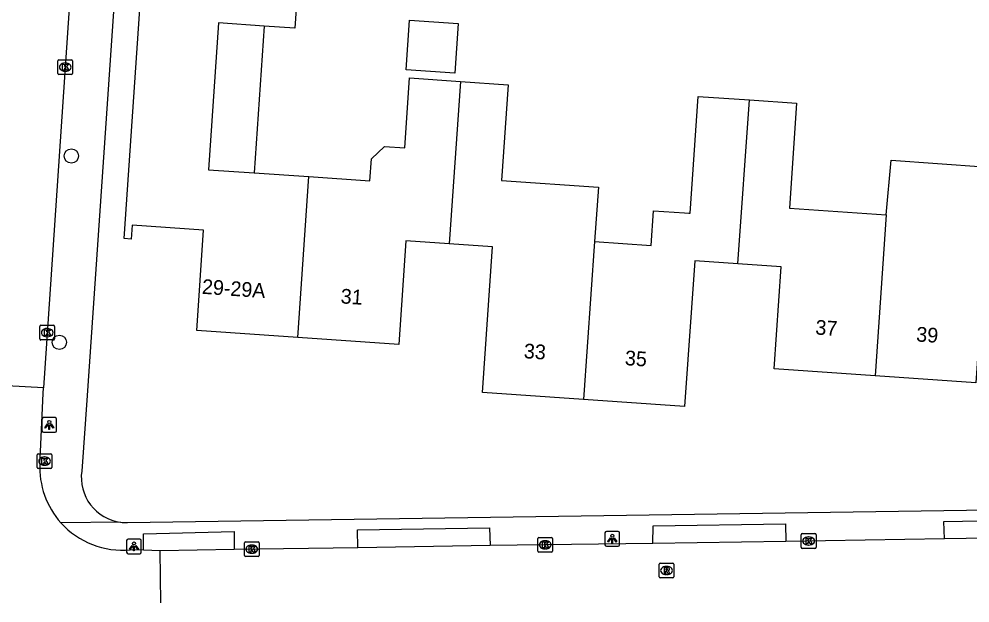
# Model space of a CAD drawing. Extents: x 161848 to 162726, y 385382 to 386521.
# Drawn here: x 162274 to 162338.6, y 385386.6 to 385426.3 of the extents above; entities that cross this region are included whole.
import ezdxf

# ---------------------------------------------------------------- set-up
doc = ezdxf.new("R2010")
doc.units = 0
for name, color, linetype in [('IMGEO_Boom', 7, 'Continuous'), ('IMGEO_Kolk', 7, 'Continuous'), ('IMGEO_Lichtpunt', 7, 'Continuous'), ('IMGEO_Pand', 7, 'Continuous'), ('IMGEO_Pand_nummerreeks', 7, 'Continuous'), ('IMGEO_Rijbaan_lokaal_open', 7, 'Continuous'), ('IMGEO_Rioolput', 7, 'Continuous'), ('IMGEO_Voetpad_open', 7, 'Continuous')]:
    doc.layers.add(name, color=color, linetype=linetype)

msp = doc.modelspace()

# ---------------------------------------------------------------- linework, layer by layer
at = {"layer": 'IMGEO_Boom'}
for centre in [(162277.545, 385416.99), (162276.731, 385404.331)]:
    msp.add_circle(centre, 0.489, dxfattribs=at)
at = {"layer": 'IMGEO_Kolk'}
for p, q in [((162276.631, 385422.602), (162276.631, 385423.454)), ((162276.706, 385423.528), (162277.558, 385423.528)), ((162277.632, 385423.454), (162277.632, 385422.602)), ((162277.119, 385423.308), (162277.144, 385423.308)), ((162277.558, 385422.528), (162276.706, 385422.528)), ((162277.142, 385422.748), (162277.117, 385422.748)), ((162275.409, 385404.563), (162275.409, 385405.415)), ((162275.484, 385405.489), (162276.336, 385405.489)), ((162276.41, 385405.415), (162276.41, 385404.563)), ((162275.92, 385404.709), (162275.895, 385404.709)), ((162275.897, 385405.269), (162275.922, 385405.269)), ((162276.336, 385404.489), (162275.484, 385404.489)), ((162275.228, 385395.837), (162275.228, 385396.689)), ((162275.303, 385396.763), (162276.155, 385396.763)), ((162275.716, 385396.543), (162275.741, 385396.543)), ((162276.229, 385396.689), (162276.229, 385395.837)), ((162276.155, 385395.763), (162275.303, 385395.763)), ((162275.739, 385395.983), (162275.714, 385395.983)), ((162327.121, 385390.409), (162327.121, 385391.261)), ((162327.196, 385391.335), (162328.048, 385391.335)), ((162328.122, 385391.261), (162328.122, 385390.409)), ((162289.299, 385389.853), (162289.299, 385390.705)), ((162289.374, 385390.779), (162290.226, 385390.779)), ((162289.787, 385390.559), (162289.812, 385390.559)), ((162290.3, 385390.705), (162290.3, 385389.853)), ((162309.227, 385390.15), (162309.227, 385391.002)), ((162309.302, 385391.076), (162310.154, 385391.076)), ((162309.715, 385390.856), (162309.74, 385390.856)), ((162310.228, 385391.002), (162310.228, 385390.15)), ((162327.632, 385390.555), (162327.607, 385390.555)), ((162327.609, 385391.115), (162327.634, 385391.115)), ((162289.81, 385389.999), (162289.785, 385389.999)), ((162310.154, 385390.076), (162309.302, 385390.076)), ((162309.738, 385390.296), (162309.713, 385390.296)), ((162328.048, 385390.335), (162327.196, 385390.335)), ((162290.226, 385389.779), (162289.374, 385389.779))]:
    msp.add_line(p, q, dxfattribs=at)
for points in [[(162276.631, 385422.602), (162276.631, 385423.454)], [(162276.706, 385423.528), (162277.558, 385423.528)], [(162277.632, 385423.454), (162277.632, 385422.602)], [(162276.952, 385423.228), (162277.075, 385423.228), (162277.075, 385423.077), (162277.205, 385423.228), (162277.369, 385423.228), (162277.223, 385423.077), (162277.376, 385422.828), (162277.224, 385422.828), (162277.139, 385422.992), (162277.075, 385422.925), (162277.075, 385422.828), (162276.952, 385422.828), (162276.952, 385423.228)], [(162277.558, 385422.528), (162276.706, 385422.528)], [(162275.409, 385404.563), (162275.409, 385405.415)], [(162275.484, 385405.489), (162276.336, 385405.489)], [(162276.41, 385405.415), (162276.41, 385404.563)], [(162275.73, 385405.189), (162275.853, 385405.189), (162275.853, 385405.038), (162275.983, 385405.189), (162276.147, 385405.189), (162276.001, 385405.038), (162276.154, 385404.789), (162276.002, 385404.789), (162275.917, 385404.953), (162275.853, 385404.886), (162275.853, 385404.789), (162275.73, 385404.789), (162275.73, 385405.189)], [(162276.336, 385404.489), (162275.484, 385404.489)], [(162275.228, 385395.837), (162275.228, 385396.689)], [(162275.303, 385396.763), (162276.155, 385396.763)], [(162275.549, 385396.463), (162275.672, 385396.463), (162275.672, 385396.312), (162275.802, 385396.463), (162275.966, 385396.463), (162275.82, 385396.312), (162275.973, 385396.063), (162275.821, 385396.063), (162275.736, 385396.227), (162275.672, 385396.16), (162275.672, 385396.063), (162275.549, 385396.063), (162275.549, 385396.463)], [(162276.229, 385396.689), (162276.229, 385395.837)], [(162276.155, 385395.763), (162275.303, 385395.763)], [(162327.121, 385390.409), (162327.121, 385391.261)], [(162327.196, 385391.335), (162328.048, 385391.335)], [(162328.122, 385391.261), (162328.122, 385390.409)], [(162289.299, 385389.853), (162289.299, 385390.705)], [(162289.374, 385390.779), (162290.226, 385390.779)], [(162290.3, 385390.705), (162290.3, 385389.853)], [(162309.227, 385390.15), (162309.227, 385391.002)], [(162309.302, 385391.076), (162310.154, 385391.076)], [(162309.548, 385390.776), (162309.671, 385390.776), (162309.671, 385390.625), (162309.801, 385390.776), (162309.965, 385390.776), (162309.819, 385390.625), (162309.972, 385390.376), (162309.82, 385390.376), (162309.735, 385390.54), (162309.671, 385390.473), (162309.671, 385390.376), (162309.548, 385390.376), (162309.548, 385390.776)], [(162310.228, 385391.002), (162310.228, 385390.15)], [(162327.442, 385391.035), (162327.565, 385391.035), (162327.565, 385390.884), (162327.695, 385391.035), (162327.859, 385391.035), (162327.713, 385390.884), (162327.866, 385390.635), (162327.714, 385390.635), (162327.629, 385390.799), (162327.565, 385390.732), (162327.565, 385390.635), (162327.442, 385390.635), (162327.442, 385391.035)], [(162289.62, 385390.479), (162289.743, 385390.479), (162289.743, 385390.328), (162289.873, 385390.479), (162290.037, 385390.479), (162289.891, 385390.328), (162290.044, 385390.079), (162289.892, 385390.079), (162289.807, 385390.243), (162289.743, 385390.176), (162289.743, 385390.079), (162289.62, 385390.079), (162289.62, 385390.479)], [(162310.154, 385390.076), (162309.302, 385390.076)], [(162328.048, 385390.335), (162327.196, 385390.335)], [(162290.226, 385389.779), (162289.374, 385389.779)]]:
    msp.add_lwpolyline(points, dxfattribs=at)
for centre, start, end in [((162276.708, 385423.452), 91.55205, 178.44795), ((162276.708, 385423.452), 91.55205, 178.44795), ((162277.556, 385423.452), 1.55205, 88.44795), ((162277.556, 385423.452), 1.55205, 88.44795), ((162276.708, 385422.604), 181.55205, 268.44795), ((162276.708, 385422.604), 181.55205, 268.44795), ((162277.556, 385422.604), 271.55205, 358.44795), ((162277.556, 385422.604), 271.55205, 358.44795), ((162275.486, 385405.413), 91.55205, 178.44795), ((162275.486, 385405.413), 91.55205, 178.44795), ((162276.334, 385405.413), 1.55205, 88.44795), ((162276.334, 385405.413), 1.55205, 88.44795), ((162275.486, 385404.565), 181.55205, 268.44795), ((162275.486, 385404.565), 181.55205, 268.44795), ((162276.334, 385404.565), 271.55205, 358.44795), ((162276.334, 385404.565), 271.55205, 358.44795), ((162275.305, 385396.687), 91.55205, 178.44795), ((162275.305, 385396.687), 91.55205, 178.44795), ((162276.153, 385396.687), 1.55205, 88.44795), ((162276.153, 385396.687), 1.55205, 88.44795), ((162275.305, 385395.839), 181.55205, 268.44795), ((162275.305, 385395.839), 181.55205, 268.44795), ((162276.153, 385395.839), 271.55205, 358.44795), ((162276.153, 385395.839), 271.55205, 358.44795), ((162327.198, 385391.259), 91.55205, 178.44795), ((162327.198, 385391.259), 91.55205, 178.44795), ((162328.046, 385391.259), 1.55205, 88.44795), ((162328.046, 385391.259), 1.55205, 88.44795), ((162289.376, 385390.703), 91.55205, 178.44795), ((162289.376, 385390.703), 91.55205, 178.44795), ((162290.224, 385390.703), 1.55205, 88.44795), ((162290.224, 385390.703), 1.55205, 88.44795), ((162309.304, 385391), 91.55205, 178.44795), ((162309.304, 385391), 91.55205, 178.44795), ((162310.152, 385391), 1.55205, 88.44795), ((162310.152, 385391), 1.55205, 88.44795), ((162289.376, 385389.855), 181.55205, 268.44795), ((162289.376, 385389.855), 181.55205, 268.44795), ((162290.224, 385389.855), 271.55205, 358.44795), ((162290.224, 385389.855), 271.55205, 358.44795), ((162309.304, 385390.152), 181.55205, 268.44795), ((162309.304, 385390.152), 181.55205, 268.44795), ((162310.152, 385390.152), 271.55205, 358.44795), ((162310.152, 385390.152), 271.55205, 358.44795), ((162327.198, 385390.411), 181.55205, 268.44795), ((162327.198, 385390.411), 181.55205, 268.44795), ((162328.046, 385390.411), 271.55205, 358.44795), ((162328.046, 385390.411), 271.55205, 358.44795)]:
    msp.add_arc(centre, 0.0765, start, end, dxfattribs=at)
for centre, major_axis, ratio, start_param, end_param in [((162277.118, 385423.028), (-0.387, 0.002), 0.722429, 4.712389, 7.853982), ((162277.143, 385423.028), (-0.39, 0.002), 0.717154, 1.570796, 4.712389), ((162275.896, 385404.989), (-0.387, 0.002), 0.722429, 4.712389, 7.853982), ((162275.921, 385404.989), (-0.39, 0.002), 0.717154, 1.570796, 4.712389), ((162275.715, 385396.263), (-0.387, 0.002), 0.722429, 4.712389, 7.853982), ((162275.74, 385396.263), (-0.39, 0.002), 0.717154, 1.570796, 4.712389), ((162289.786, 385390.279), (-0.387, 0.002), 0.722429, 4.712389, 7.853982), ((162289.811, 385390.279), (-0.39, 0.002), 0.717154, 1.570796, 4.712389), ((162309.714, 385390.576), (-0.387, 0.002), 0.722429, 4.712389, 7.853982), ((162309.739, 385390.576), (-0.39, 0.002), 0.717154, 1.570796, 4.712389), ((162327.608, 385390.835), (-0.387, 0.002), 0.722429, 4.712389, 7.853982), ((162327.633, 385390.835), (-0.39, 0.002), 0.717154, 1.570796, 4.712389)]:
    msp.add_ellipse(centre, major_axis=major_axis, ratio=ratio, start_param=start_param, end_param=end_param, dxfattribs=at)
at = {"layer": 'IMGEO_Lichtpunt'}
for p, q in [((162275.55, 385399.121), (162275.55, 385398.314)), ((162275.55, 385399.121), (162275.55, 385398.314)), ((162276.452, 385399.216), (162275.644, 385399.216)), ((162276.452, 385399.216), (162275.644, 385399.216)), ((162276.546, 385398.314), (162276.546, 385399.121)), ((162276.546, 385398.314), (162276.546, 385399.121)), ((162275.644, 385398.22), (162276.452, 385398.22)), ((162275.644, 385398.22), (162276.452, 385398.22)), ((162313.787, 385391.39), (162313.787, 385390.583)), ((162313.787, 385391.39), (162313.787, 385390.583)), ((162314.689, 385391.485), (162313.881, 385391.485)), ((162314.689, 385391.485), (162313.881, 385391.485)), ((162314.783, 385390.583), (162314.783, 385391.39)), ((162314.783, 385390.583), (162314.783, 385391.39)), ((162281.3, 385390.874), (162281.3, 385390.067)), ((162281.3, 385390.874), (162281.3, 385390.067)), ((162282.202, 385390.969), (162281.394, 385390.969)), ((162282.202, 385390.969), (162281.394, 385390.969)), ((162282.296, 385390.067), (162282.296, 385390.874)), ((162282.296, 385390.067), (162282.296, 385390.874)), ((162313.881, 385390.489), (162314.689, 385390.489)), ((162313.881, 385390.489), (162314.689, 385390.489)), ((162281.394, 385389.973), (162282.202, 385389.973)), ((162281.394, 385389.973), (162282.202, 385389.973))]:
    msp.add_line(p, q, dxfattribs=at)
for points in [[(162275.924, 385398.785), (162275.963, 385398.757), (162275.775, 385398.495), (162275.737, 385398.522), (162275.924, 385398.785)], [(162276.026, 385398.737), (162276.073, 385398.737), (162276.073, 385398.415), (162276.026, 385398.415), (162276.026, 385398.737)], [(162276.136, 385398.757), (162276.174, 385398.784), (162276.361, 385398.522), (162276.322, 385398.494), (162276.136, 385398.757)], [(162281.674, 385390.538), (162281.713, 385390.51), (162281.525, 385390.248), (162281.487, 385390.275), (162281.674, 385390.538)], [(162281.776, 385390.49), (162281.823, 385390.49), (162281.823, 385390.168), (162281.776, 385390.168), (162281.776, 385390.49)], [(162281.886, 385390.51), (162281.924, 385390.537), (162282.111, 385390.275), (162282.072, 385390.247), (162281.886, 385390.51)], [(162314.161, 385391.054), (162314.2, 385391.026), (162314.012, 385390.764), (162313.974, 385390.791), (162314.161, 385391.054)], [(162314.263, 385391.006), (162314.31, 385391.006), (162314.31, 385390.684), (162314.263, 385390.684), (162314.263, 385391.006)], [(162314.373, 385391.026), (162314.411, 385391.053), (162314.598, 385390.791), (162314.559, 385390.763), (162314.373, 385391.026)]]:
    msp.add_lwpolyline(points, dxfattribs=at)
for centre in [(162276.049, 385398.919), (162314.286, 385391.188), (162281.799, 385390.672)]:
    msp.add_circle(centre, 0.0994, dxfattribs=at)
for centre, start, end in [((162275.644, 385399.121), 90, 180), ((162275.644, 385399.121), 90, 180), ((162276.452, 385399.121), 0, 90), ((162276.452, 385399.121), 0, 90), ((162275.644, 385398.314), 180, 270), ((162275.644, 385398.314), 180, 270), ((162276.452, 385398.314), 270, 0), ((162276.452, 385398.314), 270, 360), ((162313.881, 385391.39), 90, 180), ((162313.881, 385391.39), 90, 180), ((162314.689, 385391.39), 0, 90), ((162314.689, 385391.39), 0, 90), ((162281.394, 385390.874), 90, 180), ((162281.394, 385390.874), 90, 180), ((162282.202, 385390.874), 0, 90), ((162282.202, 385390.874), 0, 90), ((162313.881, 385390.583), 180, 270), ((162313.881, 385390.583), 180, 270), ((162314.689, 385390.583), 270, 0), ((162314.689, 385390.583), 270, 360), ((162281.394, 385390.067), 180, 270), ((162281.394, 385390.067), 180, 270), ((162282.202, 385390.067), 270, 0), ((162282.202, 385390.067), 270, 360)]:
    msp.add_arc(centre, 0.0946, start, end, dxfattribs=at)
at = {"layer": 'IMGEO_Pand'}
for points in [[(162292.921, 385404.655), (162286.06, 385405.127), (162286.529, 385411.952), (162281.684, 385412.285), (162281.619, 385411.343), (162281.132, 385411.376), (162282.593, 385432.629), (162287.974, 385432.259), (162293.149, 385431.904), (162292.721, 385425.669), (162290.635, 385425.812)], [(162290.635, 385425.812), (162287.545, 385426.024), (162286.86, 385416.057), (162289.951, 385415.844)], [(162300.29, 385422.84), (162300.521, 385426.209), (162303.814, 385425.983), (162303.582, 385422.614), (162300.29, 385422.84)], [(162290.635, 385425.812), (162289.951, 385415.844)], [(162293.68, 385415.588), (162297.818, 385415.304), (162297.921, 385416.801), (162298.813, 385417.629), (162300.187, 385417.535), (162300.513, 385422.289), (162303.976, 385422.051)], [(162332.888, 385412.984), (162333.214, 385416.701), (162339.508, 385416.248), (162339.955, 385422.748), (162343.381, 385422.512)], [(162303.976, 385422.051), (162303.21, 385411.026)], [(162303.976, 385422.051), (162307.206, 385421.829), (162306.759, 385415.326), (162313.34, 385414.873), (162313.082, 385411.171)], [(162313.082, 385411.171), (162316.933, 385410.907), (162317.095, 385413.273), (162319.181, 385413.129), (162319.49, 385413.108), (162319.567, 385413.103), (162320.112, 385421.036), (162323.593, 385420.797)], [(162322.82, 385409.668), (162323.593, 385420.797)], [(162323.593, 385420.797), (162326.805, 385420.576), (162326.314, 385413.436), (162332.888, 385412.984)], [(162289.951, 385415.844), (162293.68, 385415.588)], [(162292.921, 385404.655), (162293.68, 385415.588)], [(162332.888, 385412.984), (162332.13, 385402.06)], [(162303.21, 385411.026), (162300.265, 385411.229), (162299.781, 385404.183), (162292.921, 385404.655)], [(162313.082, 385411.171), (162312.338, 385400.451)], [(162342.6, 385411.281), (162339.66, 385411.483), (162338.98, 385401.589), (162332.13, 385402.06)], [(162312.338, 385400.451), (162305.473, 385400.923), (162306.154, 385410.824), (162303.21, 385411.026)], [(162322.82, 385409.668), (162319.88, 385409.87), (162319.2, 385399.98), (162312.338, 385400.451)], [(162332.13, 385402.06), (162325.281, 385402.53), (162325.758, 385409.466), (162322.82, 385409.668)]]:
    msp.add_lwpolyline(points, dxfattribs=at)
at = {"layer": 'IMGEO_Rijbaan_lokaal_open'}
for points in [[(162277.92, 385434.749), (162275.656, 385401.229)], [(162275.656, 385401.229), (162270.647, 385401.514)], [(162275.409, 385396.107), (162275.452, 385396.923), (162275.631, 385400.858), (162275.656, 385401.229)], [(162305.98, 385390.533), (162297.003, 385390.375)], [(162317.048, 385390.66), (162305.98, 385390.533)], [(162326.07, 385390.811), (162317.048, 385390.66)], [(162336.847, 385390.975), (162326.07, 385390.811)], [(162345.675, 385391.109), (162336.847, 385390.975)], [(162282.456, 385390.202), (162281.549, 385390.231)], [(162283.574, 385390.167), (162282.456, 385390.202)], [(162288.6, 385390.263), (162283.574, 385390.167)], [(162283.627, 385386.624), (162283.627, 385386.624), (162283.574, 385390.167)], [(162297.003, 385390.375), (162288.6, 385390.263)]]:
    msp.add_lwpolyline(points, dxfattribs=at)
for centre, radius, start, end in [((162281.018, 385395.821), 5.616, 177.08151, 221.93652), ((162281.02, 385395.829), 5.623, 221.98056, 275.39753)]:
    msp.add_arc(centre, radius, start, end, dxfattribs=at)
at = {"layer": 'IMGEO_Rioolput'}
for p, q in [((162317.469, 385388.406), (162317.469, 385389.258)), ((162317.544, 385389.332), (162318.396, 385389.332)), ((162318.47, 385389.258), (162318.47, 385388.406)), ((162317.98, 385388.552), (162317.955, 385388.552)), ((162317.957, 385389.112), (162317.982, 385389.112)), ((162318.396, 385388.332), (162317.544, 385388.332))]:
    msp.add_line(p, q, dxfattribs=at)
for points in [[(162317.469, 385388.406), (162317.469, 385389.258)], [(162317.544, 385389.332), (162318.396, 385389.332)], [(162318.47, 385389.258), (162318.47, 385388.406)], [(162318.058, 385389.03), (162317.806, 385389.032), (162317.806, 385388.632)], [(162317.806, 385388.632), (162317.93, 385388.632), (162317.93, 385388.794), (162317.941, 385388.794)], [(162317.984, 385388.951), (162317.93, 385388.951), (162317.93, 385388.87)], [(162317.93, 385388.87), (162317.982, 385388.87)], [(162317.988, 385388.765), (162318.059, 385388.632), (162318.199, 385388.632), (162318.134, 385388.758)], [(162318.396, 385388.332), (162317.544, 385388.332)]]:
    msp.add_lwpolyline(points, dxfattribs=at)
for centre, radius, start, end in [((162317.546, 385389.256), 0.0765, 91.55205, 178.44795), ((162317.546, 385389.256), 0.0765, 91.55205, 178.44795), ((162318.394, 385389.256), 0.0765, 1.55205, 88.44795), ((162318.394, 385389.256), 0.0765, 1.55205, 88.44795), ((162317.94, 385388.741), 0.0533, 26.02933, 88.69889), ((162317.966, 385389.059), 0.19, 274.7715, 282.96867), ((162317.99, 385388.855), 0.0964, 77.00612, 93.18647), ((162318.004, 385388.912), 0.0378, 276.66336, 79.67722), ((162318.057, 385388.92), 0.109, 350.36119, 89.41601), ((162318.055, 385388.92), 0.112, 277.58423, 350.98172), ((162318.039, 385388.705), 0.108, 29.51342, 73.79051), ((162317.546, 385388.408), 0.0765, 181.55205, 268.44795), ((162317.546, 385388.408), 0.0765, 181.55205, 268.44795), ((162318.394, 385388.408), 0.0765, 271.55205, 358.44795), ((162318.394, 385388.408), 0.0765, 271.55205, 358.44795)]:
    msp.add_arc(centre, radius, start, end, dxfattribs=at)
for centre, major_axis, ratio, start_param, end_param in [((162317.956, 385388.832), (-0.387, 0.002), 0.722429, 4.712389, 7.853982), ((162317.981, 385388.832), (-0.39, 0.002), 0.717154, 1.570796, 4.712389)]:
    msp.add_ellipse(centre, major_axis=major_axis, ratio=ratio, start_param=start_param, end_param=end_param, dxfattribs=at)
at = {"layer": 'IMGEO_Voetpad_open'}
for points in [[(162280.836, 385433.091), (162278.626, 385400.728), (162278.251, 385395.589)], [(162281.355, 385392.086), (162416.901, 385394.073), (162424.16, 385394.133)], [(162280.893, 385392.111), (162276.84, 385392.068)], [(162317.048, 385390.66), (162317.055, 385391.863), (162326.046, 385392.005), (162326.07, 385390.811)], [(162336.847, 385390.975), (162336.813, 385392.155), (162345.646, 385392.311), (162345.675, 385391.109)], [(162282.456, 385390.202), (162282.445, 385391.332), (162288.604, 385391.48), (162288.6, 385390.263)], [(162297.003, 385390.375), (162296.977, 385391.591), (162305.95, 385391.733), (162305.98, 385390.533)]]:
    msp.add_lwpolyline(points, dxfattribs=at)
for centre, radius, start, end in [((162281.291, 385395.156), 3.071, 171.88912, 262.55382), ((162281.293, 385395.222), 3.137, 262.67347, 271.13173)]:
    msp.add_arc(centre, radius, start, end, dxfattribs=at)

# ---------------------------------------------------------------- texts
at = {"layer": 'IMGEO_Pand_nummerreeks'}
for s, rotation, p in [('29-29A', 356.06378, (162286.392, 385407.63)), ('31', 356.06427, (162295.812, 385406.981)), ('37', 356.07046, (162328.054, 385404.865)), ('39', 356.06951, (162334.903, 385404.394)), ('33', 356.07014, (162308.254, 385403.257)), ('35', 356.06951, (162315.116, 385402.786))]:
    msp.add_text(s, height=1, rotation=rotation, dxfattribs=at).set_placement(p)

doc.saveas('drawing.dxf')
